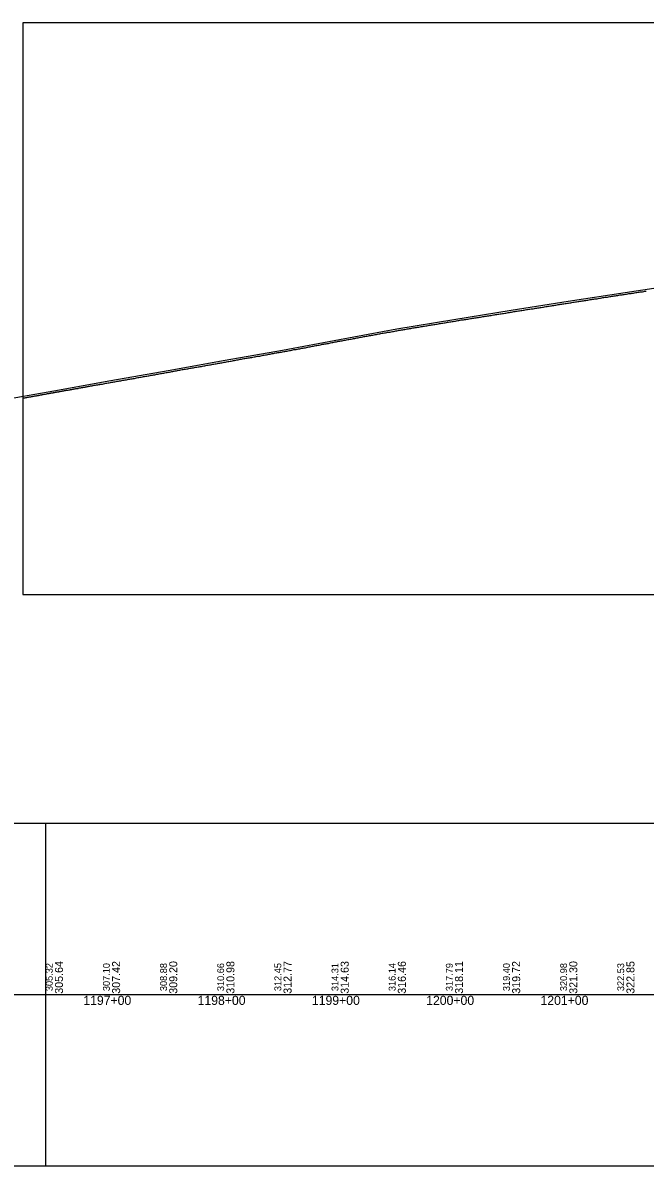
# Model space of a CAD drawing. Extents: x -3627 to 47473, y 2850 to 4350.
# Drawn here: x 7000 to 7545, y 2850 to 3850 of the extents above; entities that cross this region are included whole.
import ezdxf

# ---------------------------------------------------------------- set-up
doc = ezdxf.new("R2010")
doc.units = 0
for name, color, linetype in [('RD_DDB_Profile_EX', 7, 'Continuous'), ('RD_DDB_Profile_PR', 7, 'Continuous'), ('RD_DDB_StaTX', 7, 'Continuous'), ('RD_DDB_StripGrade', 7, 'Continuous'), ('RD_GPK_Profile_Cell', 7, 'Continuous'), ('RD_SHT_ShtClip', 7, 'Continuous')]:
    doc.layers.add(name, color=color, linetype=linetype)

msp = doc.modelspace()

# ---------------------------------------------------------------- linework, layer by layer
at = {"layer": 'RD_DDB_Profile_EX'}
for points in [[(7494.655578, 3607.498025), (7495.656649, 3607.790145), (7496.659019, 3607.896595), (7497.652054, 3608.091065), (7498.653882, 3608.24445), (7499.656299, 3608.39779), (7500.64932, 3608.54815), (7501.651162, 3608.651425), (7502.653579, 3608.75182), (7503.655995, 3608.955025), (7504.648955, 3609.155385), (7505.650816, 3609.302985), (7506.693889, 3609.456145), (7507.686581, 3609.653745), (7508.68865, 3609.806835), (7509.690188, 3610.00453), (7510.692337, 3610.10754), (7511.683638, 3610.213715), (7512.685196, 3610.31147), (7513.687267, 3610.55927), (7514.67992, 3610.707065), (7515.681491, 3610.80996), (7516.683563, 3610.91529), (7517.676202, 3611.158195), (7518.678269, 3611.30615), (7519.679858, 3611.45898), (7520.681929, 3611.659375), (7521.674551, 3611.857345), (7522.676153, 3612.00776), (7523.449568, 3612.056295), (7524.452016, 3612.15446), (7525.454465, 3612.404925), (7526.456913, 3612.50762), (7527.449388, 3612.655785), (7528.451836, 3612.762815), (7529.453594, 3613.00969), (7530.446068, 3613.157965), (7531.448517, 3613.266745), (7532.450965, 3613.413005), (7533.453413, 3613.515455), (7534.445887, 3613.713785), (7535.447642, 3613.816915), (7536.45009, 3614.01539), (7537.490287, 3614.219595), (7538.445039, 3614.31614), (7539.447486, 3614.46284), (7540.449568, 3614.61881), (7541.44171, 3614.76811), (7542.444157, 3614.825525), (7543.446604, 3615.0724), (7544.448712, 3615.22107), (7545.441525, 3615.36973)], [(7394.765127, 3591.76884), (7395.758351, 3591.961175), (7396.760707, 3592.060775), (7397.763159, 3592.211215), (7398.756378, 3592.27773), (7399.758029, 3592.5661), (7400.760412, 3592.62454), (7401.762862, 3592.91307), (7402.75528, 3593.06745), (7403.75851, 3593.30514), (7404.760893, 3593.417495), (7405.753311, 3593.57183), (7406.811651, 3593.721775), (7407.892094, 3593.833885), (7408.808077, 3594.017845), (7409.887766, 3594.129975), (7410.812912, 3594.40615), (7411.883438, 3594.47995), (7412.808559, 3594.571765), (7413.81097, 3594.852805), (7414.804923, 3594.97182), (7415.806616, 3595.16055), (7416.809758, 3595.26795), (7417.803038, 3595.452745), (7418.805405, 3595.57183), (7419.807878, 3595.73001), (7420.801831, 3595.92181), (7421.881467, 3596.13002), (7422.806666, 3596.221845), (7423.877139, 3596.391665), (7424.802313, 3596.62182), (7425.87322, 3596.73787), (7426.867546, 3596.93753), (7427.868766, 3597.08791), (7428.872226, 3597.23762), (7429.86508, 3597.426315), (7430.868543, 3597.57597), (7431.869766, 3597.73029), (7432.786014, 3597.775975), (7433.865956, 3598.03426), (7434.868648, 3598.09172), (7435.861501, 3598.330435), (7436.864963, 3598.48011), (7437.866956, 3598.584395), (7438.860508, 3598.649555), (7439.862502, 3598.93829), (7440.788274, 3599.16859), (7441.857926, 3599.29223), (7442.861386, 3599.434225), (7443.863382, 3599.534625), (7444.857698, 3599.73813), (7445.858929, 3599.88466), (7446.862388, 3599.94208), (7447.855237, 3600.142385), (7448.78133, 3600.326645), (7449.859812, 3600.442515), (7450.854123, 3600.734495), (7451.856118, 3600.78872), (7452.858816, 3600.94228), (7453.851666, 3601.142585), (7454.855125, 3601.33847), (7455.856365, 3601.43884), (7456.773614, 3601.623095), (7457.852549, 3601.79275), (7458.856008, 3601.942485), (7459.848097, 3602.09278), (7460.851555, 3602.23868), (7461.844401, 3602.40044), (7462.847103, 3602.546375), (7463.772777, 3602.68525), (7464.673824, 3602.838945), (7465.675516, 3603.03247), (7466.677931, 3603.17916), (7467.670378, 3603.37583), (7468.672794, 3603.52998), (7469.675209, 3603.684085), (7470.667656, 3603.923515), (7471.670071, 3604.03124), (7472.672431, 3604.135335), (7473.674847, 3604.235755), (7474.667294, 3604.432565), (7475.66971, 3604.57948), (7476.672126, 3604.833445), (7477.664573, 3604.93034), (7478.666989, 3605.084265), (7479.669405, 3605.19158), (7480.661741, 3605.43256), (7481.663484, 3605.58637), (7482.665901, 3605.73681), (7483.668317, 3605.980645), (7484.660763, 3606.084345), (7485.66318, 3606.19459), (7486.665596, 3606.34175), (7487.658684, 3606.488895), (7488.660409, 3606.639385), (7489.662825, 3606.84933), (7490.6559, 3606.9965), (7491.657689, 3607.140645), (7492.660105, 3607.294185), (7493.662521, 3607.435375), (7494.655578, 3607.498025)], [(7294.581948, 3574.79872), (7295.575663, 3574.999215), (7296.576845, 3575.112285), (7297.579187, 3575.262925), (7298.581622, 3575.557235), (7299.57343, 3575.76475), (7300.575864, 3575.91527), (7301.578299, 3576.097485), (7302.570671, 3576.3042), (7303.573106, 3576.460815), (7304.575541, 3576.57944), (7305.577976, 3576.72991), (7306.569781, 3576.96921), (7307.572128, 3577.208015), (7308.574563, 3577.36447), (7309.567026, 3577.50906), (7310.569461, 3577.67132), (7311.571809, 3577.904495), (7312.574244, 3578.02247), (7313.566047, 3578.179525), (7314.568482, 3578.46859), (7315.570917, 3578.61344), (7316.563296, 3578.852715), (7317.565731, 3578.953325), (7318.568167, 3579.10955), (7319.569939, 3579.322245), (7320.562402, 3579.47824), (7321.564754, 3579.58988), (7322.56719, 3579.86842), (7323.568537, 3580.018975), (7324.562089, 3580.169465), (7325.564524, 3580.41461), (7326.565147, 3580.56631), (7327.558677, 3580.72215), (7328.561112, 3580.91741), (7329.563548, 3581.112715), (7330.564934, 3581.268575), (7331.558368, 3581.4192), (7332.560804, 3581.61979), (7333.561545, 3581.726515), (7334.555034, 3581.916755), (7335.557394, 3582.17258), (7336.559829, 3582.318095), (7337.561258, 3582.463645), (7338.554729, 3582.664195), (7339.556493, 3582.770885), (7340.55787, 3582.97654), (7341.551318, 3583.172135), (7342.553754, 3583.327635), (7343.555218, 3583.433085), (7344.557659, 3583.5788), (7345.551018, 3583.72942), (7346.55278, 3583.900055), (7347.849363, 3584.200295), (7348.788895, 3584.386615), (7349.782332, 3584.54171), (7350.783778, 3584.642245), (7351.787006, 3584.791755), (7352.78036, 3584.937535), (7353.78181, 3585.092755), (7354.784272, 3585.338555), (7355.777612, 3585.493665), (7356.779153, 3585.644105), (7357.781536, 3585.744645), (7358.784765, 3585.98495), (7359.777184, 3586.13545), (7360.779644, 3586.2905), (7361.782027, 3586.45014), (7362.774445, 3586.555105), (7363.776904, 3586.755515), (7364.780058, 3586.996115), (7365.772552, 3587.091985), (7366.774935, 3587.24255), (7367.777393, 3587.397475), (7368.778891, 3587.552445), (7369.772267, 3587.75281), (7370.774649, 3587.812115), (7371.776925, 3588.19411), (7372.770297, 3588.294505), (7373.772678, 3588.449445), (7374.774267, 3588.558595), (7375.767551, 3588.66336), (7376.770005, 3588.85944), (7377.7723, 3589.063395), (7378.774759, 3589.11379), (7379.768034, 3589.38846), (7380.770415, 3589.56467), (7381.772022, 3589.71506), (7382.765284, 3589.90702), (7383.768516, 3590.1023), (7384.770055, 3590.15706), (7385.763385, 3590.35743), (7386.765765, 3590.516315), (7387.767315, 3590.666785), (7388.760631, 3590.858835), (7389.763011, 3590.963475), (7390.765418, 3591.108875), (7391.767802, 3591.305275), (7392.761108, 3591.505665), (7393.762675, 3591.61436), (7394.765127, 3591.76884)], [(7194.503275, 3556.41714), (7195.504874, 3556.606855), (7196.499387, 3556.78471), (7197.498909, 3556.908335), (7198.500508, 3557.09827), (7199.494361, 3557.23829), (7200.493917, 3557.428285), (7201.495515, 3557.62963), (7202.489507, 3557.78073), (7203.491091, 3557.914765), (7204.490515, 3558.13341), (7205.484466, 3558.334515), (7206.486048, 3558.417985), (7207.485509, 3558.569115), (7208.480062, 3558.876985), (7209.481645, 3559.02061), (7210.483227, 3559.20079), (7211.475012, 3559.37269), (7212.476593, 3559.57384), (7213.478343, 3559.764525), (7214.471997, 3559.875935), (7215.471536, 3560.116895), (7216.473282, 3560.297725), (7217.466897, 3560.47917), (7218.466473, 3560.720325), (7219.46887, 3560.850825), (7220.462455, 3560.952125), (7221.464183, 3561.243465), (7222.4638, 3561.36441), (7223.457346, 3561.55594), (7224.45907, 3561.69748), (7225.458724, 3561.948885), (7226.45223, 3562.09074), (7227.45395, 3562.279855), (7228.455512, 3562.462305), (7229.447263, 3562.663425), (7230.4495, 3562.795465), (7231.451062, 3562.965415), (7232.444639, 3563.075725), (7233.444371, 3563.349685), (7234.445932, 3563.510215), (7235.439467, 3563.570395), (7236.439236, 3563.98609), (7237.440943, 3564.155235), (7238.434288, 3564.274245), (7239.435833, 3564.31048), (7240.435798, 3564.676795), (7241.429103, 3564.8281), (7242.431344, 3564.954415), (7243.431338, 3565.27141), (7244.424611, 3565.455905), (7245.426155, 3565.56584), (7246.427839, 3565.742105), (7247.419417, 3565.893335), (7248.421098, 3566.0863), (7249.540212, 3566.337705), (7250.532572, 3566.6059), (7251.534421, 3566.773415), (7252.536757, 3566.92409), (7253.538491, 3567.083515), (7254.530967, 3567.14975), (7255.532701, 3567.511845), (7256.535152, 3567.67804), (7257.528458, 3567.802725), (7258.529252, 3568.03785), (7259.546368, 3568.18924), (7260.548772, 3568.4321), (7261.541208, 3568.640155), (7262.542928, 3568.87634), (7263.545332, 3568.99946), (7264.546929, 3569.15828), (7265.539365, 3569.25866), (7266.541082, 3569.545075), (7267.543485, 3569.68821), (7268.543629, 3569.896985), (7269.537517, 3570.097415), (7270.539229, 3570.29151), (7271.541632, 3570.399205), (7272.541923, 3570.66473), (7273.535663, 3570.85815), (7274.538066, 3571.06569), (7275.538377, 3571.216855), (7276.540785, 3571.44635), (7277.533915, 3571.59765), (7278.534831, 3571.81898), (7279.536548, 3571.920165), (7280.530345, 3572.150115), (7281.532047, 3572.364985), (7282.533108, 3572.60199), (7283.534713, 3572.753495), (7284.528476, 3572.99067), (7285.528863, 3573.105315), (7286.531269, 3573.312385), (7287.585693, 3573.443715), (7288.579352, 3573.700835), (7289.580494, 3573.851365), (7290.582928, 3573.958345), (7291.585363, 3574.17169), (7292.57773, 3574.40943), (7293.579513, 3574.567135), (7294.581948, 3574.79872)], [(7094.814548, 3538.617625), (7095.809696, 3538.73191), (7096.808515, 3538.88258), (7097.810828, 3539.060725), (7098.805956, 3539.35531), (7099.80452, 3539.533945), (7100.806834, 3539.67042), (7101.808436, 3539.83492), (7102.803529, 3539.99891), (7103.803107, 3540.199165), (7104.804707, 3540.327105), (7105.807019, 3540.572795), (7106.798662, 3540.73707), (7107.800974, 3540.88736), (7108.803286, 3541.110585), (7109.802197, 3541.238325), (7110.607172, 3541.401815), (7111.60936, 3541.60208), (7112.611547, 3541.73892), (7113.603798, 3541.989165), (7114.606878, 3542.152465), (7115.609066, 3542.229505), (7116.601318, 3542.42969), (7117.604399, 3542.67609), (7118.606587, 3542.85311), (7119.601489, 3543.053345), (7120.601028, 3543.2036), (7121.603786, 3543.39032), (7122.598679, 3543.564005), (7123.598228, 3543.7378), (7124.601311, 3543.890735), (7125.596198, 3544.10424), (7126.595755, 3544.254495), (7127.597945, 3544.465145), (7128.593719, 3544.614975), (7129.595905, 3544.81531), (7130.595474, 3545.00246), (7131.591241, 3545.14182), (7132.593107, 3545.429105), (7133.592686, 3545.56628), (7134.587545, 3545.753475), (7135.590632, 3545.91644), (7136.590219, 3546.10367), (7137.585071, 3546.29319), (7138.58816, 3546.529995), (7139.590348, 3546.69336), (7140.5826, 3546.83057), (7141.584788, 3546.99389), (7142.587878, 3547.18075), (7143.579814, 3547.36818), (7144.582004, 3547.531475), (7145.488771, 3547.68138), (7146.483755, 3547.855755), (7147.483314, 3548.04336), (7148.485454, 3548.16968), (7149.481078, 3548.38083), (7150.480651, 3548.544275), (7151.483019, 3548.781815), (7152.478407, 3548.90747), (7153.480545, 3549.0208), (7154.480363, 3549.08389), (7155.475086, 3549.34608), (7156.477883, 3549.534335), (7157.477714, 3549.733745), (7158.472428, 3549.92236), (7159.47545, 3550.07222), (7160.477594, 3550.26004), (7161.469776, 3550.46051), (7162.472143, 3550.635645), (7163.474945, 3550.84827), (7164.46713, 3551.01135), (7165.469498, 3551.17425), (7166.472302, 3551.38661), (7167.467205, 3551.57443), (7168.466859, 3551.66253), (7169.469011, 3551.86319), (7170.464558, 3552.00038), (7171.466705, 3552.21337), (7172.466381, 3552.338685), (7173.461917, 3552.588835), (7174.464067, 3552.751805), (7175.46397, 3552.939795), (7176.458622, 3553.17733), (7177.461434, 3553.31501), (7178.463802, 3553.490735), (7179.455994, 3553.691255), (7180.458807, 3553.853545), (7181.520768, 3554.016965), (7182.519951, 3554.167955), (7183.521568, 3554.432755), (7184.515802, 3554.62171), (7185.518015, 3554.810365), (7186.517433, 3554.97341), (7187.511444, 3555.136495), (7188.513046, 3555.32591), (7189.514837, 3555.441775), (7190.506471, 3555.701545), (7191.508072, 3555.879475), (7192.509858, 3556.107455), (7193.501491, 3556.293255), (7194.503275, 3556.41714)], [(7030.979685, 3527.236955), (7031.64668, 3527.372145), (7031.974266, 3527.421285), (7032.649289, 3527.522545), (7032.97274, 3527.588105), (7033.648508, 3527.75689), (7033.974884, 3527.83841), (7034.650849, 3527.97409), (7034.976147, 3528.022885), (7035.646707, 3528.12445), (7035.968361, 3528.173165), (7036.645806, 3528.30919), (7036.969621, 3528.341625), (7037.64842, 3528.477345), (7037.971764, 3528.590375), (7038.651034, 3528.692255), (7038.970709, 3528.740665), (7039.643375, 3528.80912), (7039.965233, 3528.85739), (7040.645988, 3529.027405), (7040.967375, 3529.075615), (7041.648326, 3529.144305), (7041.968211, 3529.192535), (7042.644001, 3529.294875), (7042.960423, 3529.310915), (7043.643426, 3529.51562), (7043.962565, 3529.595355), (7044.645763, 3529.664365), (7044.963815, 3529.759665), (7045.648377, 3529.89648), (7045.962811, 3529.944095), (7046.640715, 3530.0815), (7046.957274, 3530.128985), (7047.643328, 3530.19767), (7047.959415, 3530.24508), (7048.645942, 3530.313795), (7048.95843, 3530.392595), (7049.645138, 3530.63321), (7049.959683, 3530.680395), (7050.640892, 3530.8179), (7050.954599, 3530.89654), (7051.643098, 3531.03474), (7051.952742, 3531.081635), (7052.642596, 3531.1507), (7052.954887, 3531.213115), (7053.645214, 3531.316635), (7053.957032, 3531.3634), (7054.64066, 3531.467425), (7054.948348, 3531.514015), (7055.841748, 3531.69889), (7056.53421, 3531.837815), (7056.840307, 3531.915005), (7057.526972, 3532.05356), (7057.835732, 3532.099865), (7058.529755, 3532.20394), (7058.838042, 3532.25017), (7059.532482, 3532.389495), (7059.836618, 3532.404915), (7060.532199, 3532.509275), (7060.838932, 3532.60118), (7061.52797, 3532.740775), (7061.833646, 3532.817105), (7062.530754, 3532.991175), (7062.832925, 3533.02172), (7063.53049, 3533.12636), (7063.835239, 3533.202465), (7064.533227, 3533.272795), (7064.83687, 3533.30318), (7065.529025, 3533.40799), (7065.832238, 3533.43834), (7066.830561, 3533.68929), (7067.531496, 3533.79442), (7067.832874, 3533.83962), (7068.527271, 3533.909795), (7068.82822, 3533.93992), (7069.826859, 3534.105635), (7070.829172, 3534.391015), (7071.830795, 3534.54179), (7072.823153, 3534.76237), (7073.825465, 3534.907235), (7074.827086, 3535.093185), (7075.829397, 3535.25827), (7076.821061, 3535.44425), (7077.823084, 3535.59477), (7078.825396, 3535.75974), (7079.824108, 3535.98129), (7080.819368, 3536.14617), (7081.820981, 3536.353445), (7082.823292, 3536.50385), (7083.815648, 3536.647575), (7084.817258, 3536.862765), (7085.819569, 3537.034315), (7086.818324, 3537.135145), (7087.813532, 3537.35686), (7088.81556, 3537.57175), (7089.814336, 3537.72948), (7090.816651, 3537.879765), (7091.811123, 3537.994545), (7092.813433, 3538.274265), (7093.812938, 3538.41689), (7094.814548, 3538.617625)], [(7000.166419, 3521.792525), (7000.824908, 3521.85846), (7001.165261, 3521.927145), (7001.817617, 3522.0588), (7002.160976, 3522.1103), (7002.82034, 3522.340775), (7003.163228, 3522.39224), (7003.823062, 3522.45835), (7004.162082, 3522.543865), (7004.815771, 3522.64288), (7005.15741, 3522.677375), (7005.818426, 3522.80953), (7006.159662, 3522.826705), (7006.821149, 3522.893), (7007.158534, 3522.97811), (7007.813858, 3523.07738), (7008.15422, 3523.162395), (7008.81658, 3523.32783), (7009.156472, 3523.378825), (7009.819303, 3523.478275), (7010.155357, 3523.512255), (7010.812012, 3523.64483), (7011.15103, 3523.72952), (7011.814735, 3523.79599), (7012.153282, 3523.84678), (7012.817457, 3523.946415), (7013.155534, 3524.01399), (7013.81354, 3524.146795), (7014.147471, 3524.21448), (7014.812822, 3524.31428), (7015.149723, 3524.41521), (7015.815545, 3524.614675), (7016.151975, 3524.64836), (7016.811611, 3524.748275), (7017.144282, 3524.832175), (7017.810977, 3524.932155), (7018.146534, 3524.99921), (7018.8137, 3525.132535), (7019.148787, 3525.182785), (7019.809752, 3525.28287), (7020.141093, 3525.333045), (7020.809131, 3525.53321), (7021.143346, 3525.60002), (7021.811854, 3525.666955), (7022.145598, 3525.733655), (7022.814577, 3525.867355), (7023.144183, 3525.90093), (7023.80722, 3526.001355), (7024.139793, 3526.05125), (7024.809943, 3526.218645), (7025.142046, 3526.3016), (7025.812666, 3526.368745), (7026.144299, 3526.385415), (7026.808684, 3526.519535), (7027.136606, 3526.585735), (7027.646794, 3526.686595), (7027.977401, 3526.75269), (7028.649404, 3526.92057), (7028.979541, 3526.98658), (7029.651736, 3527.088055), (7029.977541, 3527.15383), (7030.651067, 3527.18767), (7030.979685, 3527.236955)]]:
    msp.add_lwpolyline(points, dxfattribs=at)
at = {"layer": 'RD_DDB_Profile_PR'}
msp.add_lwpolyline([(6427.33, 3425.168), (6477.33, 3432.897), (6527.33, 3441.112), (6577.33, 3449.5955), (6627.33, 3458.0615), (6677.33, 3466.4845), (6727.33, 3475.3245), (6777.33, 3484.1725), (6827.33, 3492.9045), (6877.33, 3501.6185), (6927.33, 3510.423), (6977.33, 3519.4385), (7027.33, 3528.224), (7077.33, 3537.1205), (7127.33, 3546.009), (7177.33, 3554.897), (7227.33, 3563.8565), (7277.33, 3573.1665), (7327.33, 3582.2865), (7377.33, 3590.5735), (7427.33, 3598.607), (7477.33, 3606.4975), (7527.33, 3614.238), (7577.33, 3621.821)], dxfattribs=at)
at = {"layer": 'RD_GPK_Profile_Cell'}
msp.add_line((1000, 3000), (46705.077602, 3000), dxfattribs=at)
at = {"layer": 'RD_SHT_ShtClip'}
for points in [[(8500.165, 3350), (8500.165, 3850), (8500.165, 3850), (7000.33, 3850), (7000.33, 3350)], [(5480.33, 3150), (7020, 3150), (7020, 2850), (5480.33, 2850)], [(6980.33, 3150), (8520, 3150), (8520, 2850), (6980.33, 2850)]]:
    msp.add_lwpolyline(points, close=True, dxfattribs=at)

# ---------------------------------------------------------------- texts
at = {"layer": 'RD_DDB_StaTX'}
for s, p in [('1197+00', (7053.125471, 2991)), ('1198+00', (7153.125471, 2991)), ('1199+00', (7253.125471, 2991)), ('1200+00', (7353.125471, 2991)), ('1201+00', (7453.125471, 2991))]:
    msp.add_text(s, height=8, dxfattribs=at).set_placement(p)
at = {"layer": 'RD_DDB_StripGrade'}
for s, height, p in [('305.32', 6, (7026.33, 3003.073688)), ('305.64', 7, (7035.33, 3000.75)), ('307.10', 6, (7076.33, 3003.073688)), ('307.42', 7, (7085.33, 3000.75)), ('308.88', 6, (7126.33, 3003.073688)), ('309.20', 7, (7135.33, 3000.75)), ('310.66', 6, (7176.33, 3003.073688)), ('310.98', 7, (7185.33, 3000.75)), ('312.45', 6, (7226.33, 3003.073688)), ('312.77', 7, (7235.33, 3000.75)), ('314.31', 6, (7276.33, 3003.073688)), ('314.63', 7, (7285.33, 3000.75)), ('316.14', 6, (7326.33, 3003.073688)), ('316.46', 7, (7335.33, 3000.75)), ('317.79', 6, (7376.33, 3003.073688)), ('318.11', 7, (7385.33, 3000.75)), ('319.40', 6, (7426.33, 3003.073688)), ('319.72', 7, (7435.33, 3000.75)), ('320.98', 6, (7476.33, 3003.073688)), ('321.30', 7, (7485.33, 3000.75)), ('322.53', 6, (7526.33, 3003.073688)), ('322.85', 7, (7535.33, 3000.75))]:
    msp.add_text(s, height=height, rotation=90, dxfattribs=at).set_placement(p)

doc.saveas('drawing.dxf')
